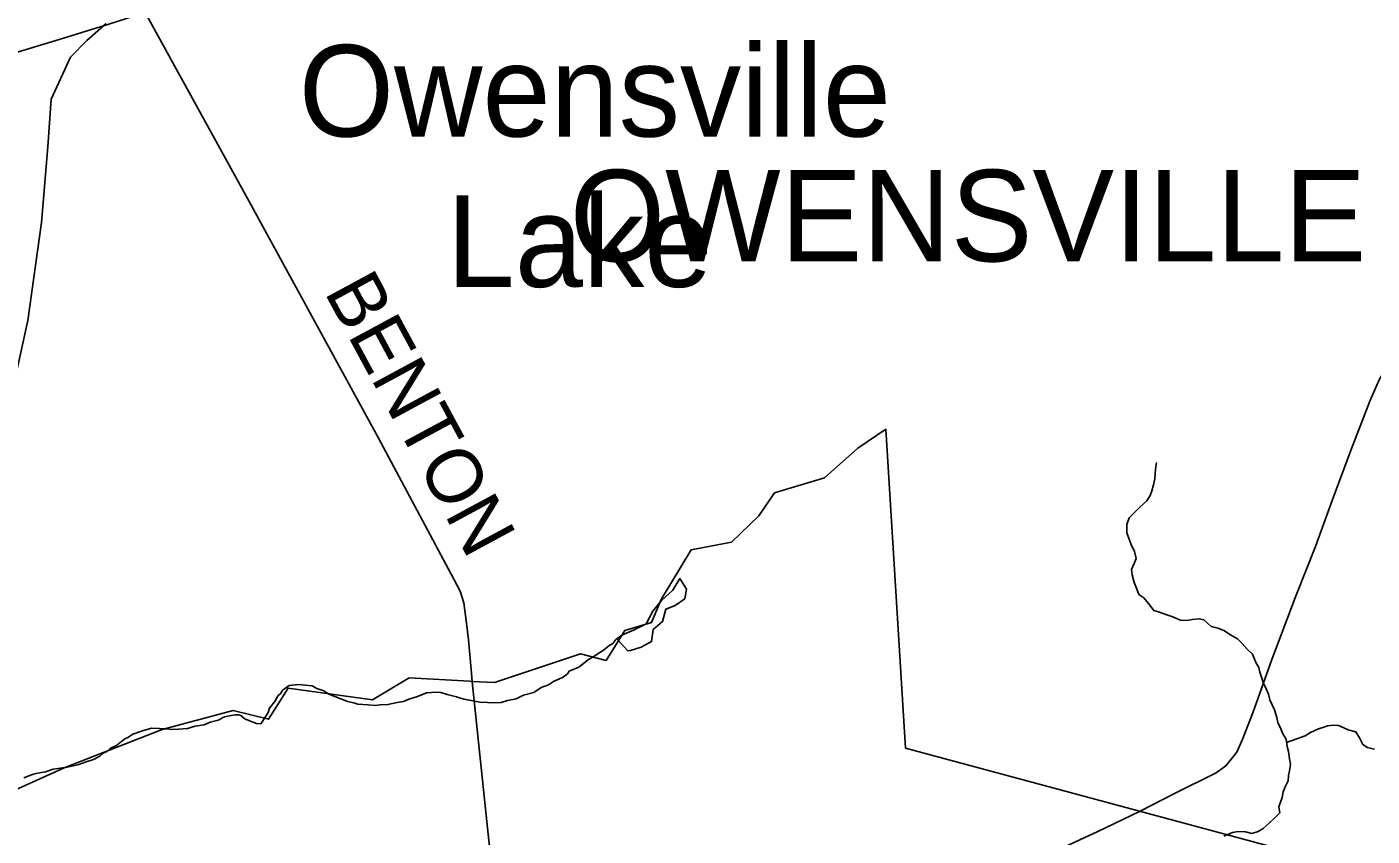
# Model space of a CAD drawing. Extents: x 0 to 34, y 0 to 22.
# Drawn here: x 6.245 to 7.636, y 19.158 to 19.995 of the extents above; entities that cross this region are included whole.
import ezdxf

# ---------------------------------------------------------------- set-up
doc = ezdxf.new("R2010")
doc.units = 0
for name, color, linetype in [('GM_X_Corporation', 7, 'Continuous'), ('GM_X_Corporation_Text', 7, 'Continuous'), ('GM_X_County_Road', 7, 'Continuous'), ('GM_X_Minor_Lake', 7, 'Continuous'), ('GM_X_Minor_Lake_Text', 7, 'Continuous'), ('GM_X_Minor_River', 7, 'Continuous'), ('GM_X_Rail_Line', 7, 'Continuous'), ('GM_X_State_Route', 7, 'Continuous'), ('GM_X_Township_Road_Text', 7, 'Continuous'), ('GM_X_US_Route', 7, 'Continuous')]:
    doc.layers.add(name, color=color, linetype=linetype)

msp = doc.modelspace()

# ---------------------------------------------------------------- linework, layer by layer
at = {"layer": 'GM_X_Corporation'}
for points in [[(7.8688, 19.0561), (7.3951, 19.184), (7.1532, 19.2492), (7.1328, 19.5791), (7.104, 19.5594), (7.0694, 19.5287), (7.0179, 19.5132), (7.0016, 19.4895), (6.9734, 19.4622), (6.9315, 19.4544), (6.9004, 19.4029), (6.8906, 19.3791), (6.8631, 19.3708), (6.8437, 19.3399), (6.8172, 19.3468), (6.7282, 19.317), (6.7051, 19.3182), (6.7023, 19.3183), (6.6401, 19.3217), (6.6021, 19.2991), (6.5149, 19.3113), (6.4947, 19.279), (6.458, 19.2879), (6.3847, 19.2685), (6.2834, 19.2286), (6.2142, 19.1977)], [(6.2142, 19.1977), (6.2834, 19.2286), (6.3847, 19.2685), (6.458, 19.2879), (6.4947, 19.279), (6.5149, 19.3113), (6.6021, 19.2991), (6.6401, 19.3217), (6.7023, 19.3183), (6.7051, 19.3182), (6.7282, 19.317), (6.8172, 19.3468), (6.8437, 19.3399), (6.8631, 19.3708), (6.8906, 19.3791), (6.9004, 19.4029), (6.9315, 19.4544), (6.9734, 19.4622), (7.0016, 19.4895), (7.0179, 19.5132), (7.0694, 19.5287), (7.104, 19.5594), (7.1328, 19.5791), (7.1532, 19.2492), (7.3951, 19.184), (7.8688, 19.0561)]]:
    msp.add_lwpolyline(points, dxfattribs=at)
at = {"layer": 'GM_X_County_Road'}
for points in [[(6.7045, 19.3266), (6.7015, 19.3611), (6.6992, 19.3785), (6.6966, 19.3995), (6.6926, 19.4115), (6.6836, 19.4292), (6.6081, 19.5704), (6.4746, 19.8149), (6.367, 20.0102)], [(6.774, 18.6863), (6.77, 18.7002), (6.7355, 19.0285), (6.7053, 19.3177), (6.7045, 19.3266)]]:
    msp.add_lwpolyline(points, dxfattribs=at)
at = {"layer": 'GM_X_Minor_Lake'}
for points in [[(6.8546, 19.3622), (6.86, 19.366), (6.8726, 19.3715), (6.8849, 19.3777), (6.892, 19.3909), (6.9009, 19.4018), (6.9125, 19.4126), (6.92, 19.4246), (6.9266, 19.4135), (6.9249, 19.4036), (6.9149, 19.3966), (6.9053, 19.393), (6.9021, 19.3801), (6.8924, 19.3719), (6.8907, 19.3594), (6.8799, 19.3535)], [(6.8799, 19.3535), (6.8688, 19.3503), (6.8661, 19.3499), (6.8546, 19.3622)]]:
    msp.add_lwpolyline(points, dxfattribs=at)
at = {"layer": 'GM_X_Minor_River'}
for points in [[(7.5156, 19.3377), (7.5119, 19.3465), (7.5066, 19.3515), (7.5014, 19.3573), (7.4965, 19.3623), (7.4894, 19.3662), (7.4822, 19.3708), (7.4762, 19.3732), (7.4694, 19.3748), (7.4618, 19.3818), (7.4569, 19.383), (7.4497, 19.3823), (7.4444, 19.3813), (7.4375, 19.3814), (7.4285, 19.3853), (7.4224, 19.3873), (7.4148, 19.3901), (7.4099, 19.3916), (7.4043, 19.3986), (7.3995, 19.4047), (7.3946, 19.4082), (7.392, 19.4147), (7.3898, 19.4204), (7.3876, 19.4284), (7.387, 19.4341), (7.3897, 19.4402), (7.3917, 19.4454), (7.3899, 19.4527), (7.3866, 19.4599), (7.3844, 19.4653), (7.3822, 19.4718), (7.3819, 19.4805), (7.3843, 19.4873), (7.3955, 19.4985), (7.4028, 19.5049), (7.4063, 19.5105), (7.4079, 19.5154), (7.4095, 19.5215), (7.4111, 19.5279), (7.4115, 19.5336), (7.412, 19.5404), (7.4128, 19.5446)], [(6.5087, 19.3086), (6.5161, 19.3138), (6.5256, 19.3148), (6.5324, 19.3143), (6.5396, 19.3134), (6.5445, 19.3107), (6.5517, 19.3083), (6.557, 19.3048), (6.5694, 19.3), (6.5762, 19.2972), (6.5827, 19.2959), (6.5868, 19.2947), (6.5975, 19.2938), (6.6047, 19.2933), (6.61, 19.2939), (6.618, 19.2942), (6.6275, 19.2963), (6.634, 19.2973), (6.6398, 19.2999), (6.6485, 19.3024), (6.6581, 19.3064), (6.6631, 19.3067), (6.6665, 19.307), (6.6729, 19.3065), (6.6794, 19.3045), (6.6888, 19.3021), (6.6964, 19.2996), (6.7063, 19.298), (6.7131, 19.2967), (6.7211, 19.2962), (6.7271, 19.2961), (6.7351, 19.2963), (6.7416, 19.2985), (6.7508, 19.3002), (6.7584, 19.3039), (6.7688, 19.3067), (6.7764, 19.3119), (6.7841, 19.3145), (6.7891, 19.3182), (6.7994, 19.3226), (6.8037, 19.3259), (6.8056, 19.3289), (6.8156, 19.3329), (6.8256, 19.3407), (6.8294, 19.343), (6.8371, 19.3481), (6.8406, 19.35), (6.8464, 19.3548), (6.8506, 19.3574), (6.8537, 19.3616), (6.8546, 19.3622)], [(7.4823, 19.1579), (7.4914, 19.1619), (7.4972, 19.163), (7.5047, 19.1625), (7.5112, 19.1609), (7.5177, 19.1627), (7.523, 19.166), (7.5292, 19.1716), (7.535, 19.1768), (7.5404, 19.1821), (7.5393, 19.1885), (7.5425, 19.198), (7.5437, 19.204), (7.5457, 19.2089), (7.5488, 19.2153), (7.5493, 19.2207), (7.5501, 19.2256), (7.5513, 19.2324), (7.5503, 19.2381), (7.5492, 19.2457), (7.5478, 19.2507), (7.5468, 19.2583), (7.5434, 19.264), (7.5412, 19.269), (7.5383, 19.2755), (7.5372, 19.2808), (7.5346, 19.2888), (7.5324, 19.2938), (7.5299, 19.2991), (7.5284, 19.3049), (7.5262, 19.3106), (7.5233, 19.3163), (7.5196, 19.3278), (7.5185, 19.3327), (7.5156, 19.3377)], [(6.2415, 19.2182), (6.2495, 19.2215), (6.2541, 19.223), (6.264, 19.2247), (6.272, 19.2272), (6.277, 19.2279), (6.2861, 19.2293), (6.2942, 19.231), (6.2984, 19.2321), (6.306, 19.235), (6.3137, 19.2375), (6.3202, 19.2408), (6.3236, 19.2438), (6.3275, 19.2456), (6.3313, 19.249), (6.3375, 19.2519), (6.3459, 19.2586), (6.349, 19.2601), (6.3544, 19.2634), (6.3643, 19.2671), (6.3735, 19.2696), (6.3819, 19.2694), (6.3853, 19.269), (6.3898, 19.2689), (6.3944, 19.2684), (6.4016, 19.2687), (6.4108, 19.2693), (6.4188, 19.2718), (6.4279, 19.2732), (6.4344, 19.2761), (6.4425, 19.2782), (6.449, 19.2815), (6.4558, 19.2829), (6.46, 19.2836), (6.4635, 19.2836), (6.4661, 19.2828), (6.4706, 19.2789), (6.4736, 19.2781), (6.4766, 19.2765), (6.4823, 19.2745), (6.4865, 19.2744), (6.4888, 19.2774), (6.4943, 19.2861), (6.4955, 19.2906), (6.501, 19.2974), (6.5045, 19.3034), (6.5072, 19.3056), (6.5087, 19.3086)], [(7.5472, 19.2548), (7.5664, 19.2619), (7.5721, 19.2653), (7.5802, 19.2689), (7.5859, 19.2707), (7.5894, 19.2722), (7.5958, 19.2728), (7.6008, 19.2724), (7.6064, 19.27), (7.611, 19.268), (7.6189, 19.266), (7.6226, 19.2598), (7.6248, 19.2556), (7.6259, 19.2529), (7.6308, 19.2498), (7.635, 19.2486), (7.638, 19.2481)]]:
    msp.add_lwpolyline(points, dxfattribs=at)
at = {"layer": 'GM_X_Rail_Line'}
msp.add_lwpolyline([(6.3266, 19.9988), (6.3068, 19.9813), (6.29, 19.9641), (6.2698, 19.9205), (6.2663, 19.8713), (6.26, 19.7931), (6.2458, 19.6916), (6.2238, 19.5908)], dxfattribs=at)
at = {"layer": 'GM_X_State_Route'}
for points in [[(7.4466, 19.2097), (7.4585, 19.2155), (7.4744, 19.2234), (7.4843, 19.2308), (7.4957, 19.2449), (7.5021, 19.2589), (7.5125, 19.2856), (7.5319, 19.3407), (7.5571, 19.4075), (7.5772, 19.4578), (7.5944, 19.5054), (7.6139, 19.5582), (7.6334, 19.6081), (7.6431, 19.6301), (7.6529, 19.6476), (7.6661, 19.6688), (7.6952, 19.7146), (7.7103, 19.7369), (7.7275, 19.7647), (7.7425, 19.7893), (7.7545, 19.8078), (7.7561, 19.8104)], [(7.17, 19.073), (7.1826, 19.0818), (7.2161, 19.1), (7.2535, 19.119), (7.29, 19.1347), (7.3148, 19.1455), (7.3521, 19.1629), (7.3953, 19.1834), (7.4319, 19.2025), (7.4466, 19.2097)]]:
    msp.add_lwpolyline(points, dxfattribs=at)
at = {"layer": 'GM_X_US_Route'}
msp.add_lwpolyline([(6.2178, 19.9642), (6.2737, 19.9811), (6.3294, 19.9984), (6.367, 20.0102)], dxfattribs=at)

# ---------------------------------------------------------------- texts
at = {"layer": 'GM_X_Corporation_Text'}
msp.add_text('OWENSVILLE', height=0.0947, rotation=0, dxfattribs=at).set_placement((6.8061, 19.7528))
at = {"layer": 'GM_X_Minor_Lake_Text'}
for s, p in [('Owensville', (6.5259, 19.882)), ('Lake', (6.6789, 19.7264))]:
    msp.add_text(s, height=0.0947, rotation=359.9992, dxfattribs=at).set_placement(p)
at = {"layer": 'GM_X_Township_Road_Text'}
msp.add_text('BENTON', height=0.05682, rotation=298.3811, dxfattribs=at).set_placement((6.5516, 19.7214))

doc.saveas('drawing.dxf')
